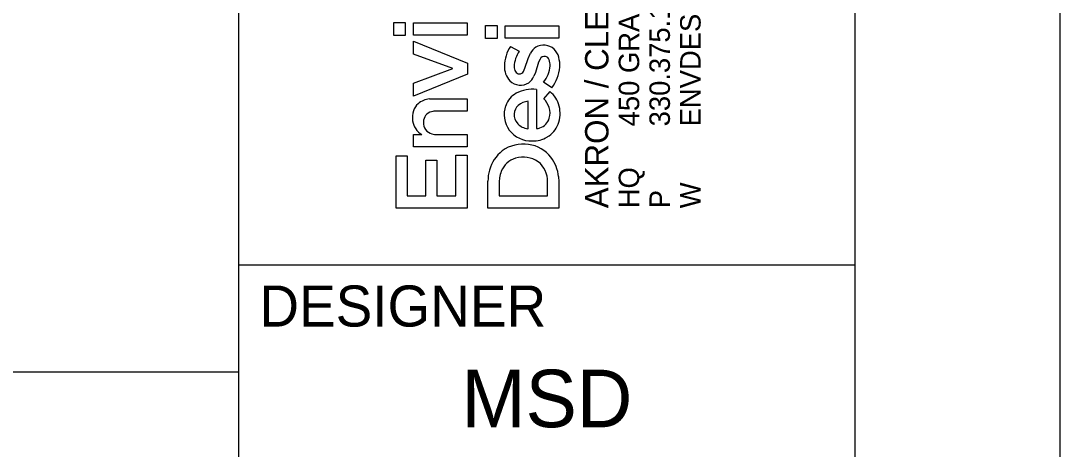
# Model space of a CAD drawing. Extents: x -2.6 to 34, y 0 to 22.
# Drawn here: x 31.469 to 34, y 2.552 to 3.594 of the extents above; entities that cross this region are included whole.
import ezdxf

# ---------------------------------------------------------------- set-up
doc = ezdxf.new("R2010")
doc.units = 0
for name, color, linetype in [('SH_Border', 7, 'Continuous'), ('SH_Cut_Line', 7, 'Continuous'), ('SH_Data', 7, 'Continuous')]:
    doc.layers.add(name, color=color, linetype=linetype)

msp = doc.modelspace()

# ---------------------------------------------------------------- linework, layer by layer
at = {"layer": 'SH_Border'}
for p, q in [((32, 0.5), (32, 21.5)), ((32, 3), (33.5, 3))]:
    msp.add_line(p, q, dxfattribs=at)
msp.add_lwpolyline([(1.5, 21.5), (33.5, 21.5), (33.5, 0.5), (1.5, 0.5)], close=True, dxfattribs=at)
at = {"layer": 'SH_Cut_Line'}
msp.add_lwpolyline([(0, 0), (34, 0), (34, 22), (0, 22)], close=True, dxfattribs=at)
at = {"layer": 'SH_Data'}
for p, q in [((32.3771, 3.5582), (32.3771, 3.5903)), ((32.3771, 3.5903), (32.4054, 3.5903)), ((32.4054, 3.5903), (32.4054, 3.5582)), ((32.4254, 3.5594), (32.4254, 3.5893)), ((32.4254, 3.5893), (32.5557, 3.5893)), ((32.5557, 3.5893), (32.5557, 3.5594)), ((32.6005, 3.5511), (32.6005, 3.5832)), ((32.6005, 3.5832), (32.6289, 3.5832)), ((32.6289, 3.5832), (32.6289, 3.5511)), ((32.6489, 3.5523), (32.6489, 3.5822)), ((32.6489, 3.5822), (32.7792, 3.5822)), ((32.7792, 3.5822), (32.7792, 3.5523)), ((32.4054, 3.5582), (32.3771, 3.5582)), ((32.5557, 3.5594), (32.4254, 3.5594)), ((32.4254, 3.5133), (32.4254, 3.5446)), ((32.4254, 3.5446), (32.5567, 3.4913)), ((32.6289, 3.5511), (32.6005, 3.5511)), ((32.7792, 3.5523), (32.6489, 3.5523)), ((32.6615, 3.5321), (32.6827, 3.5203)), ((32.5212, 3.478), (32.4254, 3.5133)), ((32.6967, 3.4787), (32.7048, 3.5026)), ((32.7048, 3.5026), (32.7104, 3.5153)), ((32.7298, 3.4933), (32.7221, 3.4688)), ((32.7334, 3.501), (32.7298, 3.4933)), ((32.4254, 3.4429), (32.5212, 3.478)), ((32.5567, 3.4913), (32.5567, 3.4644)), ((32.693, 3.4712), (32.6967, 3.4787)), ((32.7221, 3.4688), (32.7182, 3.4592)), ((32.5567, 3.4644), (32.4254, 3.4109)), ((32.4254, 3.4109), (32.4254, 3.4429)), ((32.7621, 3.4314), (32.742, 3.4447)), ((32.7245, 3.4275), (32.7246, 3.3319)), ((32.7423, 3.4046), (32.7577, 3.422)), ((32.4644, 3.404), (32.4729, 3.4044)), ((32.4729, 3.4044), (32.5557, 3.4044)), ((32.5557, 3.4044), (32.5557, 3.3746)), ((32.7049, 3.3318), (32.7049, 3.3983)), ((32.5557, 3.3746), (32.4814, 3.3746)), ((32.4254, 3.2875), (32.4254, 3.3173)), ((32.4254, 3.3173), (32.4455, 3.3173)), ((32.4822, 3.3173), (32.5557, 3.3173)), ((32.5557, 3.3173), (32.5557, 3.2876)), ((32.7036, 3.3317), (32.7049, 3.3318)), ((32.383, 3.1379), (32.383, 3.266)), ((32.383, 3.266), (32.4101, 3.266)), ((32.4101, 3.266), (32.4101, 3.1683)), ((32.5557, 3.2876), (32.4254, 3.2875)), ((32.5286, 3.1683), (32.5286, 3.2672)), ((32.5286, 3.2672), (32.5557, 3.2672)), ((32.5557, 3.2672), (32.5557, 3.1379)), ((32.455, 3.1683), (32.455, 3.2549)), ((32.455, 3.2549), (32.4822, 3.2549)), ((32.4822, 3.2549), (32.4822, 3.1683)), ((32.7785, 3.215), (32.7792, 3.2021)), ((32.6064, 3.138), (32.6064, 3.204)), ((32.6347, 3.2118), (32.6341, 3.2023)), ((32.6341, 3.2023), (32.6341, 3.1684)), ((32.7515, 3.1683), (32.7515, 3.2024)), ((32.7792, 3.2021), (32.7792, 3.138)), ((32.4101, 3.1683), (32.455, 3.1683)), ((32.4822, 3.1683), (32.5286, 3.1683)), ((32.6341, 3.1684), (32.7515, 3.1683)), ((32.5557, 3.1379), (32.383, 3.1379)), ((32.7792, 3.138), (32.6064, 3.138)), ((25.1966, 2.74), (32, 2.74))]:
    msp.add_line(p, q, dxfattribs=at)
for points in [[(32.3771, 3.5582), (32.3771, 3.5903), (32.4054, 3.5903), (32.4054, 3.5582)], [(32.4254, 3.5594), (32.4254, 3.5893), (32.5557, 3.5893), (32.5557, 3.5594)], [(32.6005, 3.5511), (32.6005, 3.5832), (32.6289, 3.5832), (32.6289, 3.5511)], [(32.6489, 3.5523), (32.6489, 3.5822), (32.7792, 3.5822), (32.7792, 3.5523)], [(32.4254, 3.4109), (32.4254, 3.4429), (32.5212, 3.478), (32.4254, 3.5133), (32.4254, 3.5446), (32.5567, 3.4913), (32.5567, 3.4644)], [(32.383, 3.1379), (32.383, 3.266), (32.4101, 3.266), (32.4101, 3.1683), (32.455, 3.1683), (32.455, 3.2549), (32.4822, 3.2549), (32.4822, 3.1683), (32.5286, 3.1683), (32.5286, 3.2672), (32.5557, 3.2672), (32.5557, 3.1379)]]:
    msp.add_lwpolyline(points, close=True, dxfattribs=at)
for points in [[(32.6615, 3.5321), (32.6827, 3.5203)], [(32.693, 3.4712), (32.6967, 3.4787), (32.7048, 3.5026), (32.7104, 3.5153)], [(32.7334, 3.501), (32.7298, 3.4933), (32.7221, 3.4688), (32.7182, 3.4592)], [(32.7621, 3.4314), (32.742, 3.4447)], [(32.7245, 3.4275), (32.7246, 3.3319)], [(32.7423, 3.4046), (32.7577, 3.422)], [(32.4644, 3.404), (32.4729, 3.4044), (32.5557, 3.4044), (32.5557, 3.3746), (32.4814, 3.3746)], [(32.7036, 3.3317), (32.7049, 3.3318), (32.7049, 3.3983)], [(32.4254, 3.2875), (32.4254, 3.3173), (32.4455, 3.3173)], [(32.4822, 3.3173), (32.5557, 3.3173), (32.5557, 3.2876), (32.4254, 3.2875)], [(32.7785, 3.215), (32.7792, 3.2021), (32.7792, 3.138), (32.6064, 3.138)], [(32.6064, 3.138), (32.6064, 3.204)], [(32.6347, 3.2118), (32.6341, 3.2023), (32.6341, 3.1684), (32.7515, 3.1683), (32.7515, 3.2024)]]:
    msp.add_lwpolyline(points, dxfattribs=at)
for centre, radius, start, end in [((32.7364, 3.4826), 0.0897, 146.531, 178.7571), ((32.7364, 3.4826), 0.0897, 146.531, 178.7571), ((32.7452, 3.4789), 0.0749, 146.5112, 176.9101), ((32.7452, 3.4789), 0.0749, 146.5112, 176.9101), ((32.7466, 3.4971), 0.0405, 125.5118, 153.4159), ((32.7466, 3.4971), 0.0405, 125.5118, 153.4159), ((32.7406, 3.5026), 0.0326, 80.1719, 122.5197), ((32.7406, 3.5026), 0.0326, 80.1719, 122.5197), ((32.7428, 3.4982), 0.0367, 47.7934, 84.6892), ((32.7428, 3.4982), 0.0367, 47.7934, 84.6892), ((32.7379, 3.4946), 0.0427, 14.9966, 46.2063), ((32.7379, 3.4946), 0.0427, 14.9966, 46.2063), ((32.7438, 3.4963), 0.0114, 76.6609, 155.7053), ((32.7438, 3.4963), 0.0114, 76.6609, 155.7053), ((32.744, 3.4951), 0.0126, 21.5098, 78.5262), ((32.744, 3.4951), 0.0126, 21.5098, 78.5262), ((32.7259, 3.4877), 0.0321, 354.5726, 22.068), ((32.7259, 3.4877), 0.0321, 354.5726, 22.068), ((32.7104, 3.4867), 0.0712, 355.8306, 15.3914), ((32.7104, 3.4867), 0.0712, 355.8306, 15.3914), ((32.6967, 3.4824), 0.0501, 177.5366, 222.7932), ((32.6967, 3.4824), 0.0501, 177.5366, 222.7932), ((32.6931, 3.4823), 0.0228, 178.4747, 211.0868), ((32.6931, 3.4823), 0.0228, 178.4747, 211.0868), ((32.6833, 3.4767), 0.0115, 212.2368, 268.3777), ((32.6833, 3.4767), 0.0115, 212.2368, 268.3777), ((32.6834, 3.4759), 0.0107, 267.716, 333.7337), ((32.6834, 3.4759), 0.0107, 267.716, 333.7337), ((32.6825, 3.4915), 0.0757, 321.811, 354.7969), ((32.6825, 3.4915), 0.0757, 321.811, 354.7969), ((32.6895, 3.4882), 0.0922, 321.9777, 355.8738), ((32.6895, 3.4882), 0.0922, 321.9777, 355.8738), ((32.686, 3.4753), 0.0375, 225.9854, 302.4797), ((32.686, 3.4753), 0.0375, 225.9854, 302.4797), ((32.681, 3.4758), 0.0408, 308.0877, 335.9874), ((32.681, 3.4758), 0.0408, 308.0877, 335.9874), ((32.7024, 3.3691), 0.0558, 118.8308, 160.6244), ((32.7024, 3.3691), 0.0558, 118.8308, 160.6244), ((32.7152, 3.3441), 0.0838, 83.615, 118.2876), ((32.7152, 3.3441), 0.0838, 83.615, 118.2876), ((32.7174, 3.3717), 0.0644, 13.5336, 51.3615), ((32.7174, 3.3717), 0.0644, 13.5336, 51.3615), ((32.4635, 3.3626), 0.0402, 132.2219, 161.6818), ((32.4635, 3.3626), 0.0402, 132.2219, 161.6818), ((32.4687, 3.3543), 0.0499, 94.9696, 130.2225), ((32.4687, 3.3543), 0.0499, 94.9696, 130.2225), ((32.7079, 3.3561), 0.0424, 94.008, 130.8817), ((32.7079, 3.3561), 0.0424, 94.008, 130.8817), ((32.7038, 3.3656), 0.0549, 19.0357, 45.4406), ((32.7038, 3.3656), 0.0549, 19.0357, 45.4406), ((32.4787, 3.3582), 0.056, 162.2736, 187.7919), ((32.4787, 3.3582), 0.056, 162.2736, 187.7919), ((32.4748, 3.3487), 0.025, 103.6865, 182.2187), ((32.4748, 3.3487), 0.025, 103.6865, 182.2187), ((32.4811, 3.3286), 0.046, 89.6049, 105.3284), ((32.4811, 3.3286), 0.046, 89.6049, 105.3284), ((32.7104, 3.3661), 0.0644, 160.5201, 215.7831), ((32.7104, 3.3661), 0.0644, 160.5201, 215.7831), ((32.7017, 3.365), 0.0311, 175.0013, 223.283), ((32.7017, 3.365), 0.0311, 175.0013, 223.283), ((32.7005, 3.3663), 0.0298, 132.9851, 177.179), ((32.7005, 3.3663), 0.0298, 132.9851, 177.179), ((32.7107, 3.3697), 0.047, 344.6059, 17.007), ((32.7107, 3.3697), 0.047, 344.6059, 17.007), ((32.7064, 3.3692), 0.0758, 339.3542, 13.3785), ((32.7064, 3.3692), 0.0758, 339.3542, 13.3785), ((32.4703, 3.358), 0.0476, 188.962, 238.7037), ((32.4703, 3.358), 0.0476, 188.962, 238.7037), ((32.4773, 3.3456), 0.0276, 175.5854, 255.1439), ((32.4773, 3.3456), 0.0276, 175.5854, 255.1439), ((32.7089, 3.3736), 0.0423, 225.0619, 262.7974), ((32.7089, 3.3736), 0.0423, 225.0619, 262.7974), ((32.7224, 3.3671), 0.035, 288.0077, 343.5508), ((32.7224, 3.3671), 0.035, 288.0077, 343.5508), ((32.7189, 3.3652), 0.0626, 300.9427, 338.7323), ((32.7189, 3.3652), 0.0626, 300.9427, 338.7323), ((32.4818, 3.3595), 0.0422, 254.0916, 270.5284), ((32.4818, 3.3595), 0.0422, 254.0916, 270.5284), ((32.7125, 3.3705), 0.0687, 217.7452, 271.6543), ((32.7125, 3.3705), 0.0687, 217.7452, 271.6543), ((32.7247, 3.3522), 0.0202, 269.7003, 294.8711), ((32.7247, 3.3522), 0.0202, 269.7003, 294.8711), ((32.6923, 3.2079), 0.0864, 81.194, 125.9984), ((32.6923, 3.2079), 0.0864, 81.194, 125.9984), ((32.6946, 3.2113), 0.0827, 37.8521, 82.402), ((32.6946, 3.2113), 0.0827, 37.8521, 82.402), ((32.7155, 3.3724), 0.0706, 269.2048, 300.3341), ((32.7155, 3.3724), 0.0706, 269.2048, 300.3341), ((32.6939, 3.2089), 0.0865, 127.2362, 165.148), ((32.6939, 3.2089), 0.0865, 127.2362, 165.148), ((32.6889, 3.2078), 0.054, 106.1881, 157.3861), ((32.6889, 3.2078), 0.054, 106.1881, 157.3861), ((32.6928, 3.1986), 0.0639, 55.6727, 107.2093), ((32.6928, 3.1986), 0.0639, 55.6727, 107.2093), ((32.6929, 3.205), 0.0587, 357.4662, 52.2665), ((32.6929, 3.205), 0.0587, 357.4662, 52.2665), ((32.6859, 3.2057), 0.0931, 5.7333, 37.304), ((32.6859, 3.2057), 0.0931, 5.7333, 37.304), ((32.7143, 3.2028), 0.1078, 164.7861, 179.3704), ((32.7143, 3.2028), 0.1078, 164.7861, 179.3704), ((32.6983, 3.2039), 0.0641, 157.3571, 172.9275), ((32.6983, 3.2039), 0.0641, 157.3571, 172.9275)]:
    msp.add_arc(centre, radius, start, end, dxfattribs=at)

# ---------------------------------------------------------------- texts
for s, height, p in [('450 GRANT ST., AKRON, OH  44311', 0.049846, (32.9749, 3.3374)), ('AKRON / CLEVELAND / COLUMBUS', 0.056969, (32.9001, 3.138)), ('ENVDESIGNGROUP.COM', 0.049846, (33.1244, 3.3374)), ('330.375.1390', 0.049846, (33.0497, 3.3374)), ('HQ ', 0.04985, (32.9749, 3.138)), ('W', 0.0498, (33.1244, 3.138)), ('P', 0.0498, (33.0497, 3.138))]:
    msp.add_text(s, height=height, rotation=90, dxfattribs=at).set_placement(p)
for s, height, p in [('DESIGNER', 0.1, (32.05, 2.85)), ('MSD', 0.14, (32.5422, 2.605))]:
    msp.add_text(s, height=height, dxfattribs=at).set_placement(p)

doc.saveas('drawing.dxf')
